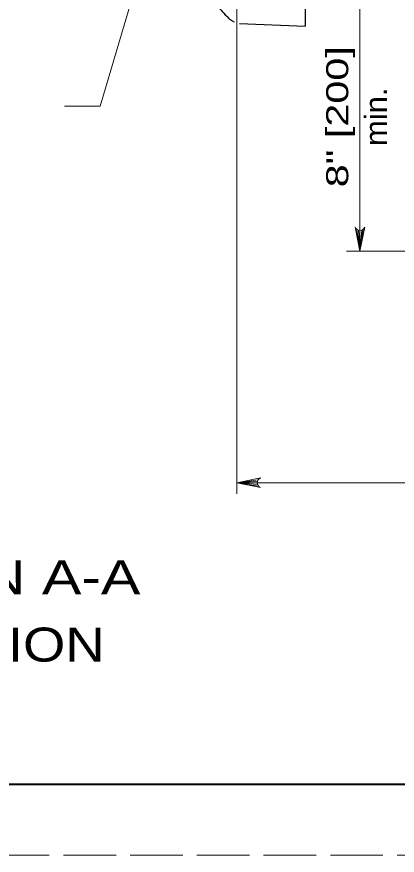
# Model space of a CAD drawing. Extents: x 1083.1 to 1117.1, y 719.4 to 741.4.
# Drawn here: x 1096.96 to 1099.65, y 719.35 to 725.28 of the extents above; entities that cross this region are included whole.
import ezdxf
from ezdxf.enums import TextEntityAlignment as Align

# ---------------------------------------------------------------- set-up
doc = ezdxf.new("R2010")
doc.units = 0
doc.header["$LTSCALE"] = 0.062
doc.linetypes.add('LONG_DASHED', pattern=[7.5, 6, -1.5])
doc.layers.add('1', color=7, linetype='Continuous', lineweight=13)

msp = doc.modelspace()

# ---------------------------------------------------------------- linework, layer by layer
at = {"layer": '1', "lineweight": 25}
for p in [(1098.99725, 727.77608), (1098.53183, 725.231)]:
    msp.add_line(p, (1098.99725, 725.21108), dxfattribs=at)
at = {"layer": '1'}
for p, q in [((1099.38367, 723.623), (1099.38367, 725.51267)), ((1097.79517, 725.48875), (1097.54492, 724.64525)), ((1098.51258, 725.34433), (1098.51258, 721.90717)), ((1097.29267, 724.64525), (1097.54492, 724.64525)), ((1099.36233, 723.77525), (1099.38367, 723.623)), ((1099.40717, 723.777), (1099.38367, 723.623)), ((1099.37292, 723.77008), (1099.38367, 723.623)), ((1099.39733, 723.77117), (1099.38367, 723.623)), ((1099.38367, 723.7685), (1099.38367, 723.623)), ((1100.50142, 723.623), (1099.28875, 723.623)), ((1098.66483, 722.00717), (1098.51258, 721.98583)), ((1098.65967, 721.99658), (1098.51258, 721.98583)), ((1098.51258, 721.98583), (1105.59625, 721.98583)), ((1098.65808, 721.98583), (1098.51258, 721.98583)), ((1098.66083, 721.97217), (1098.51258, 721.98583)), ((1098.66667, 721.96233), (1098.51258, 721.98583))]:
    msp.add_line(p, q, dxfattribs=at)
at = {"layer": '1', "linetype": 'LONG_DASHED'}
msp.add_lwpolyline([(1083.12642, 719.35408), (1117.12642, 719.35408), (1117.12642, 741.35408), (1083.12642, 741.35408)], close=True, dxfattribs=at)
at = {"layer": '1', "lineweight": 25}
msp.add_lwpolyline([(1116.62642, 719.85408), (1085.12642, 719.85408), (1085.12642, 740.85408)], dxfattribs=at)
at = {"layer": '1', "lineweight": 40}
msp.add_lwpolyline([(1085.12642, 740.85408), (1116.62642, 740.85408), (1116.62642, 719.85408), (1085.12642, 719.85408)], close=True, dxfattribs=at)
msp.add_lwpolyline([(1085.12642, 740.85408), (1116.62642, 740.85408), (1116.62642, 719.85408), (1085.12642, 719.85408)], close=True, dxfattribs=at)
at = {"layer": '1'}
for points in [[(1099.41733, 723.79117), (1099.38367, 723.623), (1099.35, 723.79117)], [(1098.68075, 721.95225), (1098.51258, 721.98583), (1098.68075, 722.0195)]]:
    msp.add_lwpolyline(points, dxfattribs=at)
for centre, start, end in [((1099.38363, 723.80472), 202.08782, 337.91395), ((1098.69434, 721.98589), 112.08782, 247.91395)]:
    msp.add_arc(centre, 0.03629, start, end, dxfattribs=at)
at = {"layer": '1', "lineweight": 25}
msp.add_spline([(1098.03317, 725.5185), (1098.14317, 725.51567), (1098.19067, 725.50333), (1098.23908, 725.48433), (1098.29133, 725.44725), (1098.36833, 725.3655), (1098.40092, 725.32367), (1098.44167, 725.28142), (1098.46925, 725.25517), (1098.49375, 725.24242)], degree=3, dxfattribs=at)

# ---------------------------------------------------------------- texts
at = {"layer": '1'}
for s, width, p in [('8" [200]', 1.4, (1099.30092, 724.57146)), ('min.', 1.05, (1099.57492, 724.5715))]:
    msp.add_text(s, height=0.156, rotation=90, dxfattribs=dict(at, width=width)).set_placement(p, align=Align.CENTER)
for s, width, p in [('SECTION A-A', 1.3, (1096.49704, 721.19833)), ('ELEVATION', 1.2, (1096.497, 720.72233))]:
    msp.add_text(s, height=0.24, dxfattribs=dict(at, width=width)).set_placement(p, align=Align.CENTER)

doc.saveas('drawing.dxf')
